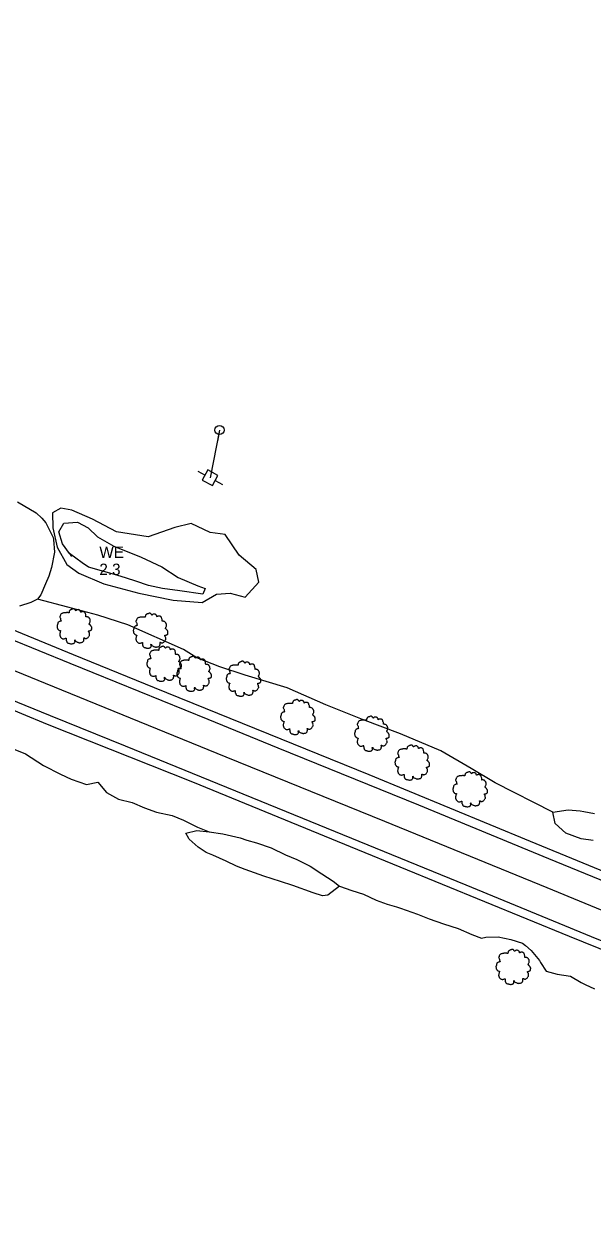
# Model space of a CAD drawing. Extents: x 2160437 to 2172832, y 205694 to 212444.
# Drawn here: x 2162620 to 2162869, y 210492 to 211016 of the extents above; entities that cross this region are included whole.
import ezdxf

# ---------------------------------------------------------------- set-up
doc = ezdxf.new("R2010")
doc.units = 0
for name, color, linetype in [('RD_EX_H2O_Pond', 7, 'Continuous'), ('RD_EX_H2O_txCode', 7, 'Continuous'), ('RD_EX_LaneStripe', 7, 'Continuous'), ('RD_EX_Road', 7, 'Continuous'), ('RD_EX_UT', 7, 'Continuous'), ('RD_EX_UT_Guy', 7, 'Continuous'), ('RD_EX_VEG', 7, 'Continuous'), ('RD_EX_VEG_ShrubLine', 7, 'Continuous'), ('RD_EX_VEG_TreeLine', 7, 'Continuous')]:
    doc.layers.add(name, color=color, linetype=linetype)

# ---------------------------------------------------------------- blocks, each defined once
blk = doc.blocks.new('T2')
at = {"layer": 'RD_EX_VEG'}
for points in [[(0.05, 7.21), (-0.25, 7.24), (-0.57, 7.14), (-0.82, 7.04), (-1.05, 6.96), (-1.27, 6.86), (-1.57, 6.69), (-1.8, 6.49), (-1.92, 6.24), (-1.97, 6.01), (-2.02, 5.74), (-2.02, 5.56), (-2.15, 5.54), (-2.3, 5.56), (-2.55, 5.64), (-2.8, 5.64), (-3.05, 5.64), (-3.4, 5.61), (-3.75, 5.61), (-4.02, 5.56), (-4.35, 5.51), (-4.72, 5.39), (-5.07, 5.26), (-5.37, 5.01), (-5.62, 4.54), (-5.75, 4.19), (-5.9, 3.94), (-5.75, 3.49), (-5.57, 3.14), (-5.55, 2.94), (-5.47, 2.52), (-5.37, 2.29), (-5.25, 2.09), (-5.32, 2.07), (-5.7, 2.02), (-6, 1.92), (-6.42, 1.69), (-6.64, 1.47), (-6.74, 1.14), (-6.77, 0.79), (-6.87, 0.59), (-6.94, 0.32), (-6.97, 0.24), (-7.02, -0.08), (-6.92, -0.53), (-6.89, -0.88), (-6.77, -1.11), (-6.62, -1.28), (-6.44, -1.53), (-6.05, -1.76), (-5.72, -1.86), (-5.52, -1.88), (-5.7, -2.38), (-5.75, -2.73), (-5.87, -3.13), (-5.87, -3.21), (-5.92, -3.68), (-5.77, -4.01), (-5.7, -4.38), (-5.52, -4.61), (-5.25, -4.91), (-4.92, -5.13), (-4.42, -5.26), (-4.02, -5.23), (-3.45, -5.06), (-3.2, -4.98), (-3.22, -5.16), (-3.2, -5.53), (-3.2, -5.96), (-3.05, -6.28), (-2.95, -6.56), (-2.8, -6.81), (-2.47, -7.03), (-2.07, -7.11), (-1.65, -7.26), (-1.2, -7.33), (-0.7, -7.36), (-0.1, -7.21), (0.18, -7.08), (0.28, -6.91), (0.48, -6.53), (0.43, -6.31), (0.45, -5.71), (0.55, -5.88), (0.73, -6.23), (1.23, -6.53), (1.63, -6.71), (2.1, -6.86), (2.4, -6.93), (2.88, -6.86), (3.25, -6.78), (3.63, -6.66), (3.93, -6.38), (4.1, -6.11), (4.15, -5.83), (4.23, -5.46), (4.28, -5.28)], [(4.28, -5.28), (4.2, -5.11), (4.15, -4.86), (4.23, -4.88), (4.4, -4.93), (4.68, -5.06), (4.9, -5.13), (5.23, -5.11), (5.5, -5.01), (5.95, -4.73), (6.22, -4.26), (6.5, -3.86), (6.57, -3.53), (6.52, -3.31), (6.5, -2.81), (6.3, -2.56), (6.25, -2.43), (6.15, -2.03), (6.22, -1.98), (6.5, -1.93), (6.87, -1.81), (7.15, -1.68), (7.37, -1.51), (7.45, -1.28), (7.42, -0.88), (7.47, -0.48), (7.4, -0.33), (7.3, -0.18), (7.22, 0.02), (7.07, 0.17), (6.97, 0.32), (6.87, 0.42), (6.75, 0.57), (6.57, 0.69), (6.42, 0.74), (6.37, 0.89), (6.52, 1.09), (6.57, 1.19), (6.6, 1.42), (6.82, 1.77), (6.87, 2.17), (6.82, 2.59), (6.77, 2.87), (6.62, 3.14), (6.42, 3.39), (6.3, 3.56), (6.12, 3.69), (5.8, 3.81), (5.55, 3.86), (5.2, 3.86), (5, 3.91), (5.03, 3.96), (5.03, 4.11), (5.03, 4.39), (4.95, 4.84), (4.8, 5.34), (4.8, 5.36), (4.7, 5.61), (4.48, 5.81), (4.3, 5.91), (4.1, 6.04), (3.85, 6.06), (3.55, 6.06), (3.28, 6.01), (3.08, 5.91), (2.9, 5.79), (2.83, 5.94), (2.73, 6.24), (2.68, 6.39), (2.53, 6.56), (2.3, 6.76), (1.85, 6.89), (1.23, 6.81), (0.93, 6.61), (0.78, 6.44), (0.73, 6.56), (0.53, 6.76), (0.43, 6.94), (0.25, 7.06), (0.1, 7.16), (0, 7.21)]]:
    blk.add_spline(points, degree=3, dxfattribs=at)
blk = doc.blocks.new('PP')
at = {"layer": 'RD_EX_UT'}
for p, q in [((2.49, 2.51), (-2.51, 2.51)), ((-2.51, 2.51), (-2.51, -2.49)), ((2.49, -2.49), (2.49, 2.51)), ((-5.94, -0.05), (-2.47, -0.05)), ((-2.51, -2.49), (2.49, -2.49)), ((2.42, -0.05), (6.06, -0.05))]:
    blk.add_line(p, q, dxfattribs=at)

msp = doc.modelspace()

# ---------------------------------------------------------------- linework, layer by layer
at = {"layer": 'RD_EX_H2O_Pond'}
msp.add_lwpolyline([(2162661.04, 210774.93), (2162648.59, 210778.35), (2162645.75, 210780.33), (2162640.25, 210784.39), (2162637.25, 210788.71), (2162635.54, 210793.91), (2162637.84, 210797.74), (2162643.77, 210798.17), (2162648.46, 210795.61), (2162652.49, 210791.73), (2162659.71, 210787.62), (2162671.71, 210782.78), (2162680.72, 210778.49), (2162687.87, 210773.82), (2162696.55, 210770.27), (2162699.7, 210769), (2162698.63, 210766.59), (2162688.59, 210767.99), (2162680.98, 210769.09), (2162674.89, 210770.35), (2162669.31, 210772.22), (2162665.2, 210773.63)], close=True, dxfattribs=at)
msp.add_lwpolyline([(2162640.25, 210784.39), (2162641.18, 210783.06)], dxfattribs=at)
at = {"layer": 'RD_EX_LaneStripe'}
for points in [[(2161951.75, 211004.45), (2162022.43, 210975.55), (2162093.36, 210946.6), (2162200.28, 210903.09), (2162271.12, 210873.95), (2162353.58, 210840.53), (2162424.23, 210811.38), (2162494.73, 210782.74), (2162564.71, 210754.09), (2162636.75, 210724.59)], [(2162636.75, 210724.59), (2162708.75, 210695.28), (2162778.34, 210667.06), (2162849.37, 210638.06), (2162920.98, 210608.59), (2162993.09, 210579.44), (2163064.15, 210550.49), (2163132.92, 210522.33), (2163202.41, 210493.83), (2163273.57, 210464.98), (2163344.27, 210436.03)]]:
    msp.add_lwpolyline(points, dxfattribs=at)
at = {"layer": 'RD_EX_Road'}
for points in [[(2161957.11, 211015.73), (2162023.1, 210988.55), (2162097.47, 210958.17), (2162150.06, 210936.59), (2162208.82, 210912.49), (2162262.79, 210890.42), (2162330.26, 210862.94), (2162420.47, 210826), (2162500.54, 210793.53), (2162558.83, 210769.6), (2162640.35, 210736.36)], [(2162642.04, 210739.95), (2162597.22, 210758.38), (2162560.37, 210773.92), (2162518.36, 210790.46), (2162479.71, 210805.93), (2162420.71, 210829.88), (2162355.64, 210856.76), (2162310.35, 210875.3), (2162259.77, 210896.07), (2162207.79, 210917.02), (2162142.96, 210943.58), (2162068.59, 210973.94), (2161996.47, 211003.18), (2161964.48, 211016.48)], [(2161952.19, 210986.85), (2162036.07, 210952.72), (2162109.13, 210923.09), (2162171.84, 210897.44), (2162229.37, 210873.67), (2162288.39, 210849.96), (2162336.14, 210830.5), (2162395.55, 210805.71), (2162445.87, 210785.35), (2162502.14, 210762.59), (2162558.59, 210739.72), (2162619.16, 210714.3), (2162630.46, 210709.57)], [(2162631.91, 210713.31), (2162570.64, 210738.29), (2162496.21, 210768.67), (2162436.52, 210792.96), (2162365.33, 210821.93), (2162289.79, 210852.84), (2162226.37, 210878.93), (2162153.59, 210908.85), (2162070.06, 210942.8), (2161984, 210977.78), (2161953.3, 210990.44)], [(2162640.35, 210736.36), (2162700.86, 210711.81), (2162731.48, 210699.29), (2162793.1, 210674.33), (2162850.08, 210650.72), (2162907.17, 210627.3), (2162946.61, 210611.64), (2162989.24, 210594.27), (2163028.92, 210577.94), (2163087.09, 210553.98), (2163130.66, 210536.28), (2163183.74, 210514.57), (2163230.95, 210495.29), (2163284.83, 210473.47), (2163347.49, 210448.15)], [(2163348.93, 210451.8), (2163300.48, 210471.39), (2163226.08, 210501.47), (2163152.25, 210531.86), (2163074.2, 210564.31), (2162997.42, 210595.08), (2162927.1, 210623.26), (2162842.26, 210658.17), (2162771.5, 210687.45), (2162677.52, 210725.51), (2162642.04, 210739.95)], [(2162630.46, 210709.57), (2162694.12, 210684.29), (2162766.48, 210654.75), (2162859.24, 210616.78), (2162947.93, 210580.75), (2163017.39, 210552.45), (2163075.71, 210528.36), (2163144.72, 210500.67), (2163221.65, 210469.08), (2163337.83, 210421.74)], [(2163339.36, 210424.64), (2163294.06, 210443.11), (2163235.31, 210467.18), (2163164.45, 210496.37), (2163090.27, 210526.38), (2163015.86, 210556.62), (2162943.37, 210586.27), (2162868.99, 210616.45), (2162814.11, 210639.11), (2162731.36, 210672.83), (2162664.77, 210699.92), (2162631.91, 210713.31)]]:
    msp.add_lwpolyline(points, dxfattribs=at)
at = {"layer": 'RD_EX_UT'}
msp.add_line((2162705.98, 210838.5), (2162705.14, 210833.57), dxfattribs=at)
msp.add_circle((2162705.98, 210838.5), 2, dxfattribs=at)
at = {"layer": 'RD_EX_UT_Guy'}
msp.add_lwpolyline([(2162705.98, 210838.5), (2162701.87, 210817.61)], dxfattribs=at)
at = {"layer": 'RD_EX_VEG_ShrubLine'}
for points in [[(2161959.02, 210969.02), (2162006.75, 210951.65), (2162044.26, 210936.65), (2162091.88, 210914.83), (2162144.14, 210892.02), (2162203.88, 210867.8), (2162264.51, 210842.89), (2162312.83, 210824.42), (2162346.2, 210811.68), (2162394.14, 210792.77), (2162442.18, 210771.9), (2162521.31, 210736.43), (2162557.79, 210720.45), (2162601.69, 210704.3), (2162620.98, 210696.57)], [(2162852.06, 210671.07), (2162826.7, 210683.9), (2162816.32, 210690.24), (2162802.97, 210697.96), (2162785.35, 210705.41), (2162768.65, 210711.67), (2162752.54, 210718.04), (2162735.66, 210725.52), (2162717.25, 210731.04), (2162706.14, 210734.77), (2162696.1, 210738.62), (2162690.24, 210742.3), (2162665.8, 210753.14), (2162652.61, 210757.44), (2162639.6, 210760.82), (2162626.3, 210764.34)], [(2162620.98, 210696.57), (2162628.94, 210691.54), (2162636.28, 210687.69), (2162641.04, 210685.46), (2162647.67, 210683.24), (2162652.68, 210684.13), (2162656.51, 210679.67), (2162661.77, 210676.8), (2162667.68, 210675.26), (2162673.14, 210672.97), (2162673.14, 210672.97), (2162678.37, 210671.12), (2162685.21, 210669.53), (2162690.21, 210667.55), (2162696.41, 210664.5), (2162701.39, 210662.49), (2162701.39, 210662.49)], [(2162758.61, 210638.56), (2162764, 210636.77), (2162769.1, 210635.05), (2162774.69, 210632.51), (2162779.51, 210630.68), (2162783.49, 210629.51), (2162785.33, 210628.93), (2162792.73, 210626.31), (2162797.85, 210624.34), (2162797.85, 210624.34), (2162804.11, 210622.1), (2162810.49, 210620), (2162816.5, 210617.45), (2162820.84, 210615.89), (2162822.7, 210616.32), (2162828.12, 210616.38), (2162828.12, 210616.38), (2162833.69, 210615.28), (2162833.69, 210615.28), (2162838.67, 210613.68), (2162840.02, 210612.66), (2162842.6, 210610.38), (2162846.17, 210605.98), (2162846.62, 210605.24), (2162849.12, 210601.43), (2162853.95, 210600.01), (2162859.8, 210599.16), (2162859.8, 210599.16), (2162864.51, 210596.41), (2162866.15, 210595.5), (2162870.34, 210593.58)]]:
    msp.add_lwpolyline(points, dxfattribs=at)
msp.add_lwpolyline([(2162639.05, 210779.53), (2162644.37, 210775.85), (2162655.32, 210771.1), (2162670.66, 210767.04), (2162685.71, 210763.95), (2162698.46, 210762.96), (2162704.73, 210766.53), (2162710.69, 210767), (2162717.24, 210765.28), (2162723.27, 210771.83), (2162722.04, 210777.42), (2162714.64, 210783.7), (2162708.44, 210792.69), (2162701.88, 210793.57), (2162693.56, 210797.51), (2162686.43, 210795.76), (2162674.69, 210791.75), (2162660.81, 210793.96), (2162650.41, 210799.42), (2162641.35, 210803.33), (2162636.5, 210804.29), (2162632.82, 210802.21), (2162633.02, 210795.64), (2162634.88, 210787.14)], close=True, dxfattribs=at)
at = {"layer": 'RD_EX_VEG_TreeLine'}
for points in [[(2162617.49, 210807.1), (2162625.61, 210802.17), (2162628.07, 210799.88), (2162629.83, 210797.9), (2162633.16, 210791.38), (2162633.25, 210790.5), (2162633.7, 210785.03), (2162632.34, 210778.2), (2162631.18, 210774.52), (2162629.77, 210771.07), (2162627.63, 210766.26), (2162626.3, 210764.34), (2162623.27, 210762.93), (2162618.35, 210761.28)], [(2162869.75, 210658.67), (2162864.42, 210659.36), (2162857.66, 210661.82), (2162853.02, 210666.09), (2162853.02, 210666.09), (2162852.06, 210671.07), (2162852.06, 210671.07), (2162858.68, 210672.09), (2162864.07, 210671.68), (2162865.68, 210671.39), (2162870.33, 210670.52)]]:
    msp.add_lwpolyline(points, dxfattribs=at)
msp.add_lwpolyline([(2162691.27, 210661.82), (2162696.12, 210663.03), (2162701.39, 210662.49), (2162701.39, 210662.49), (2162707.44, 210661.54), (2162715.03, 210659.74), (2162717.9, 210658.77), (2162722.24, 210657.62), (2162728.67, 210655.37), (2162734.97, 210652.4), (2162734.97, 210652.4), (2162739.92, 210650.32), (2162745.75, 210647.38), (2162750.75, 210644.08), (2162755.74, 210640.85), (2162758.61, 210638.56), (2162753.45, 210634.62), (2162751.08, 210634.41), (2162746.95, 210635.64), (2162738.14, 210638.89), (2162732.74, 210640.62), (2162732.74, 210640.62), (2162725.35, 210643), (2162717.27, 210645.86), (2162713.42, 210647.33), (2162708.88, 210649.64), (2162703.04, 210652.17), (2162700.1, 210653.36), (2162696.67, 210655.77), (2162692.69, 210659.22), (2162692.52, 210659.53)], close=True, dxfattribs=at)

# ---------------------------------------------------------------- block references
at = {"layer": 'RD_EX_UT', "xscale": 1.0199999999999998, "yscale": 1.02, "rotation": -28.43483500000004}
msp.add_blockref('PP', (2162701.87, 210817.61), dxfattribs=at)
at = {"layer": 'RD_EX_VEG', "xscale": 1.0499999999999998, "yscale": 1.0499999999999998}
for p in [(2162642.17, 210752.56), (2162675.56, 210750.64), (2162681.48, 210736.15), (2162694.63, 210731.75), (2162716.27, 210729.59), (2162740.1, 210712.8), (2162772.52, 210705.5), (2162790.22, 210692.85), (2162815.59, 210681.13), (2162834.49, 210603.3)]:
    msp.add_blockref('T2', p, dxfattribs=at)

# ---------------------------------------------------------------- texts
at = {"layer": 'RD_EX_H2O_txCode'}
for s, p in [('WE', (2162653.34, 210782.46)), ('2.3', (2162653.34, 210774.96))]:
    msp.add_text(s, height=5, dxfattribs=at).set_placement(p)

doc.saveas('drawing.dxf')
